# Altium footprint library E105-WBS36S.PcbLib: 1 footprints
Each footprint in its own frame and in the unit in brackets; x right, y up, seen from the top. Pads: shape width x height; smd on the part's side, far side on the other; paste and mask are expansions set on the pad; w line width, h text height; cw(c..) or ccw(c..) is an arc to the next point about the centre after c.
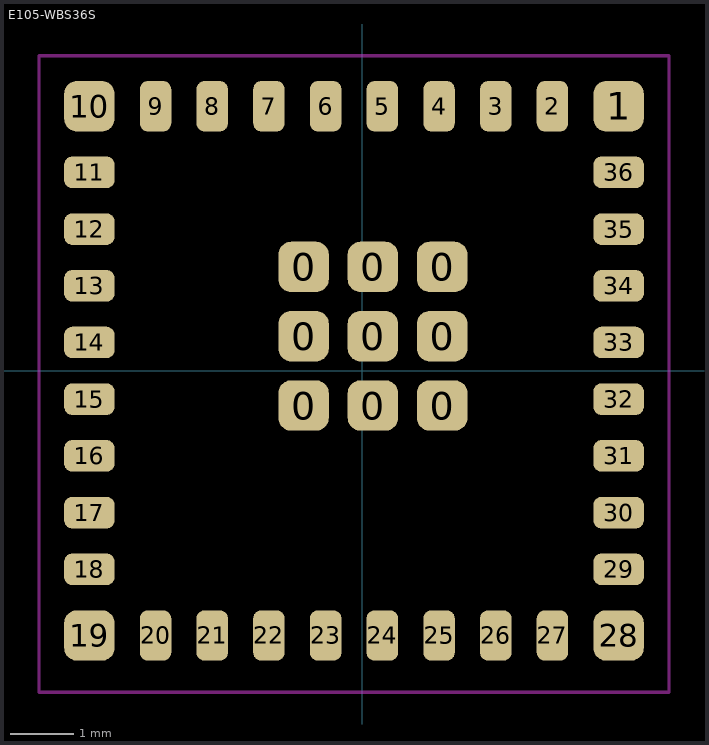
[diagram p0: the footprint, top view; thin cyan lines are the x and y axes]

## E105-WBS36S [mm]
pads (45):
  rrect50% 0.8x0.8 smd: 0(-0.927,-0.55) 0(-0.927,0.55) 0(-0.927,1.65) 0(0.173,-0.55) 0(0.173,0.55) 0(0.173,1.65) 0(1.273,-0.55) 0(1.273,0.55) 0(1.273,1.65) 1(4.073,4.2) 10(-4.327,4.2) 19(-4.327,-4.2) 28(4.073,-4.2)
  rrect50% 0.5x0.8 smd: 2(3.023,4.2) 3(2.123,4.2) 4(1.223,4.2) 5(0.323,4.2) 6(-0.577,4.2) 7(-1.477,4.2) 8(-2.377,4.2) 9(-3.277,4.2) 20(-3.277,-4.2) 21(-2.377,-4.2) 22(-1.477,-4.2) 23(-0.577,-4.2) 24(0.323,-4.2) 25(1.223,-4.2) 26(2.123,-4.2) 27(3.023,-4.2)
  rrect50% 0.8x0.5 smd: 11(-4.327,3.15) 12(-4.327,2.25) 13(-4.327,1.35) 14(-4.327,0.45) 15(-4.327,-0.45) 16(-4.327,-1.35) 17(-4.327,-2.25) 18(-4.327,-3.15) 29(4.073,-3.15) 30(4.073,-2.25) 31(4.073,-1.35) 32(4.073,-0.45) 33(4.073,0.45) 34(4.073,1.35) 35(4.073,2.25) 36(4.073,3.15)
Keep-Out Layer:
  lines w0.05: -5.127,-5.1 -5.127,5 4.873,5 4.873,-5.1 -5.127,-5.1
